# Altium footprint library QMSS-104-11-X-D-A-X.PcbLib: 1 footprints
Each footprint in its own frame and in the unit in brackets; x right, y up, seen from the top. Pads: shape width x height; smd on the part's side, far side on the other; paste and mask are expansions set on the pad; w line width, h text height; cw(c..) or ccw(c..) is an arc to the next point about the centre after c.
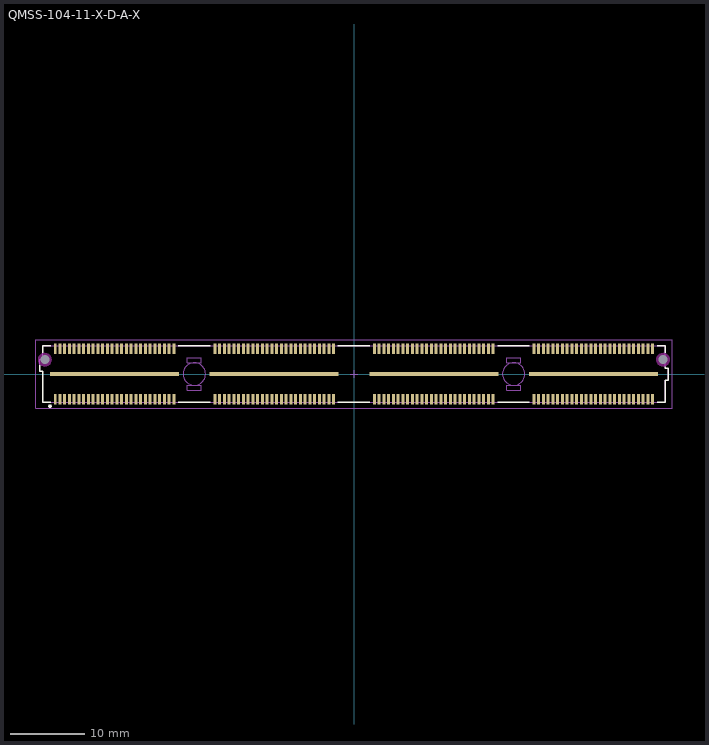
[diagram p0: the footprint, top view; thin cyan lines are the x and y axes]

## QMSS-104-11-X-D-A-X [mm] "0.635mm pitch, 208 pin, shielded header; w/4 banks, w/40 signal pin/bank, w/12 GND pin/bank"
height 6.35
pads (214):
  rect 0.4x1.4 smd mask+0: 1(-39.952,-3.365) 2(-39.952,3.365) 3(-39.317,-3.365) 4(-39.317,3.365) 5(-38.682,-3.365) 6(-38.682,3.365) 7(-38.047,-3.365) 8(-38.047,3.365) 9(-37.412,-3.365) 10(-37.412,3.365) 11(-36.777,-3.365) 12(-36.777,3.365) 13(-36.142,-3.365) 14(-36.142,3.365) 15(-35.507,-3.365) 16(-35.507,3.365) 17(-34.872,-3.365) 18(-34.872,3.365) 19(-34.237,-3.365) 20(-34.237,3.365) 21(-33.602,-3.365) 22(-33.602,3.365) 23(-32.967,-3.365) 24(-32.967,3.365) 25(-32.332,-3.365) 26(-32.332,3.365) 27(-31.697,-3.365) 28(-31.697,3.365) 29(-31.062,-3.365) 30(-31.062,3.365) 31(-30.427,-3.365) 32(-30.427,3.365) 33(-29.792,-3.365) 34(-29.792,3.365) 35(-29.157,-3.365) 36(-29.157,3.365) 37(-28.522,-3.365) 38(-28.522,3.365) 39(-27.887,-3.365) 40(-27.887,3.365) 41(-27.252,-3.365) 42(-27.252,3.365) 43(-26.617,-3.365) 44(-26.617,3.365) 45(-25.982,-3.365) 46(-25.982,3.365) 47(-25.347,-3.365) 48(-25.347,3.365) 49(-24.712,-3.365) 50(-24.712,3.365) 51(-24.077,-3.365) 52(-24.077,3.365) 53(-2.737,3.365) 54(-2.737,-3.365) 55(-3.372,3.365) 56(-3.372,-3.365) 57(-4.007,-3.365) 58(-4.007,3.365) 59(-4.642,3.365) 60(-4.642,-3.365) 61(-5.277,3.365) 62(-5.277,-3.365) 63(-5.912,3.365) 64(-5.912,-3.365) 65(-6.547,-3.365) 66(-6.547,3.365) 67(-7.182,3.365) 68(-7.182,-3.365) 69(-7.817,3.365) 70(-7.817,-3.365) 71(-8.452,3.365) 72(-8.452,-3.365) 73(-9.087,-3.365) 74(-9.087,3.365) 75(-9.722,3.365) 76(-9.722,-3.365) 77(-10.357,3.365) 78(-10.357,-3.365) 79(-10.992,3.365) 80(-10.992,-3.365) 81(-11.627,3.365) 82(-11.627,-3.365) 83(-12.262,-3.365) 84(-12.262,3.365) 85(-12.897,-3.365) 86(-12.897,3.365) 87(-13.532,3.365) 88(-13.532,-3.365) 89(-14.167,-3.365) 90(-14.167,3.365) 91(-14.802,-3.365) 92(-14.802,3.365) 93(-15.437,3.365) 94(-15.437,-3.365) 95(-16.072,-3.365) 96(-16.072,3.365) 97(-16.707,-3.365) 98(-16.707,3.365) 99(-17.342,3.365) 100(-17.342,-3.365) 101(-17.977,-3.365) 102(-17.977,3.365) 103(-18.612,3.365) 104(-18.612,-3.365) 105(18.603,3.365) 106(18.603,-3.365) 107(17.968,3.365) 108(17.968,-3.365) 109(17.333,-3.365) 110(17.333,3.365) 111(16.698,3.365) 112(16.698,-3.365) 113(16.063,3.365) 114(16.063,-3.365) 115(15.428,3.365) 116(15.428,-3.365) 117(14.793,-3.365) 118(14.793,3.365) 119(14.158,3.365) 120(14.158,-3.365) 121(13.523,3.365) 122(13.523,-3.365) 123(12.888,3.365) 124(12.888,-3.365) 125(12.253,-3.365) 126(12.253,3.365) 127(11.618,3.365) 128(11.618,-3.365) 129(10.983,3.365) 130(10.983,-3.365) 131(10.348,3.365) 132(10.348,-3.365) 133(9.713,3.365) 134(9.713,-3.365) 135(9.078,-3.365) 136(9.078,3.365) 137(8.443,-3.365) 138(8.443,3.365) 139(7.808,3.365) 140(7.808,-3.365) 141(7.173,-3.365) 142(7.173,3.365) 143(6.538,-3.365) 144(6.538,3.365) 145(5.903,3.365) 146(5.903,-3.365) 147(5.268,-3.365) 148(5.268,3.365) 149(4.633,-3.365) 150(4.633,3.365) 151(3.998,3.365) 152(3.998,-3.365) 153(3.363,-3.365) 154(3.363,3.365) 155(2.728,3.365) 156(2.728,-3.365) 157(39.943,3.365) 158(39.943,-3.365) 159(39.308,3.365) 160(39.308,-3.365) 161(38.673,-3.365) 162(38.673,3.365) 163(38.038,3.365) 164(38.038,-3.365) 165(37.403,3.365) 166(37.403,-3.365) 167(36.768,3.365) 168(36.768,-3.365) 169(36.133,-3.365) 170(36.133,3.365) 171(35.498,3.365) 172(35.498,-3.365) 173(34.863,3.365) 174(34.863,-3.365) 175(34.228,3.365) 176(34.228,-3.365) 177(33.593,-3.365) 178(33.593,3.365) 179(32.958,3.365) 180(32.958,-3.365) 181(32.323,3.365) 182(32.323,-3.365) 183(31.688,3.365) 184(31.688,-3.365) 185(31.053,3.365) 186(31.053,-3.365) 187(30.418,-3.365) 188(30.418,3.365) 189(29.783,-3.365) 190(29.783,3.365) 191(29.148,3.365) 192(29.148,-3.365) 193(28.513,-3.365) 194(28.513,3.365) 195(27.878,-3.365) 196(27.878,3.365) 197(27.243,3.365) 198(27.243,-3.365) 199(26.608,-3.365) 200(26.608,3.365) 201(25.973,-3.365) 202(25.973,3.365) 203(25.338,3.365) 204(25.338,-3.365) 205(24.703,-3.365) 206(24.703,3.365) 207(24.068,3.365) 208(24.068,-3.365)
  rect 17.25x0.5 smd mask+0: 209(-32.012,0) 210(-10.672,0) 211(10.668,0) 212(32.008,0)
  round 1 hole 1.2 unplated mask+0: 213(-41.347,1.91) 214(41.323,1.91)
Top Overlay:
  circle w0.25: c-40.65,-4.3 r0.125
  lines w0.2: -42.05,1.2 -42.05,0.35 -41.65,0.35 -41.65,-3.75 -40.55,-3.75 ; -41.65,2.85 -41.65,3.75 -40.55,3.75 ; -23.5,-3.75 -19.2,-3.75 ; -23.5,3.75 -19.2,3.75 ; -2.15,-3.75 2.1,-3.75 ; -2.15,3.75 2.1,3.75 ; 19.2,-3.75 23.45,-3.75 ; 19.2,3.75 23.45,3.75 ; 40.55,-3.75 41.65,-3.75 41.65,-0.85 42.05,-0.85 42.05,0.8 41.65,0.8 41.65,0.95 ; 40.55,3.75 41.65,3.75 41.65,2.85
Keep-Out Layer:
  pour cut-out: 42.231,1.91 42.2,2.145 42.109,2.364 41.965,2.552 41.777,2.696 41.558,2.787 41.323,2.818 41.088,2.787 40.869,2.696 40.681,2.552 40.537,2.364 40.446,2.145 40.415,1.91 40.446,1.675 40.537,1.456 40.681,1.268 40.869,1.124 41.088,1.033 41.323,1.002 41.558,1.033 41.777,1.124 41.965,1.268 42.109,1.456 42.2,1.675
  pour cut-out: -40.439,1.91 -40.47,2.145 -40.561,2.364 -40.705,2.552 -40.893,2.696 -41.112,2.787 -41.347,2.818 -41.582,2.787 -41.801,2.696 -41.989,2.552 -42.133,2.364 -42.224,2.145 -42.255,1.91 -42.224,1.675 -42.133,1.456 -41.989,1.268 -41.801,1.124 -41.582,1.033 -41.347,1.002 -41.112,1.033 -40.893,1.124 -40.705,1.268 -40.561,1.456 -40.47,1.675
Mechanical 12:
  lines w0.001: -42.05,0.35 -42.05,2 -41.65,2 -41.65,3.75 41.65,3.75 41.65,0.8 42.05,0.8 42.05,-0.85 41.65,-0.85 41.65,-3.75 -41.65,-3.75 -41.65,0.35 -42.05,0.35
Mechanical 13:
  circle w0.1: c-21.35,0 r1.5
  circle w0.1: c21.35,0 r1.5
  lines w0.1: -42.05,0.35 -42.05,2 -41.65,2 -41.65,3.75 41.65,3.75 41.65,0.8 42.05,0.8 42.05,-0.85 41.65,-0.85 41.65,-3.75 -41.65,-3.75 -41.65,0.35 -42.05,0.35 ; -22.3,-2.15 -22.3,-1.5 -20.4,-1.5 -20.4,-2.15 -22.3,-2.15 ; -22.3,1.5 -22.3,2.15 -20.4,2.15 -20.4,1.5 -22.3,1.5 ; 20.4,-2.15 20.4,-1.5 22.3,-1.5 22.3,-2.15 20.4,-2.15 ; 20.4,1.5 20.4,2.15 22.3,2.15 22.3,1.5 20.4,1.5
  text ".Designator" at 0.254,0.254 h1.52
Mechanical 15:
  lines w0.05: -0.5,0 0.5,0 ; 0,-0.5 0,0.5 ; -42.55,-4.55 -42.55,4.55 42.55,4.55 42.55,-4.55 -42.55,-4.55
